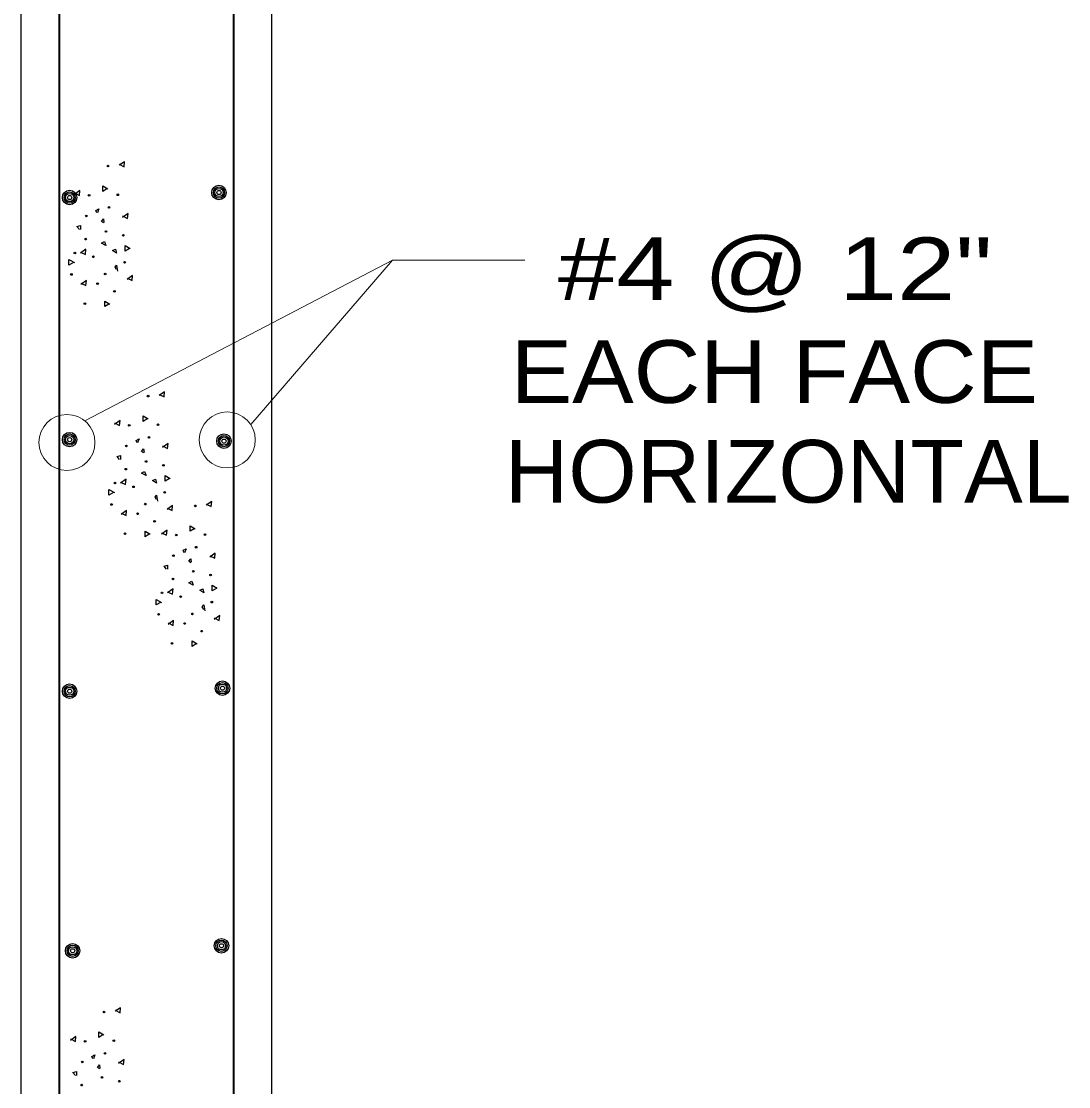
# Model space of a CAD drawing. Extents: x -28.1 to 13.9, y -16.1 to 13.9.
# Drawn here: x -22.697 to -20.607, y 4.395 to 6.521 of the extents above; entities that cross this region are included whole.
import ezdxf
from ezdxf.enums import TextEntityAlignment as Align

# ---------------------------------------------------------------- set-up
doc = ezdxf.new("R2010")
doc.units = 0
doc.header["$LTSCALE"] = 0.05
doc.layers.add('1', color=7, linetype='Continuous', lineweight=13)
doc.layers.add('2', color=7, linetype='Continuous', lineweight=13)

msp = doc.modelspace()

# ---------------------------------------------------------------- linework, layer by layer
at = {"layer": '1', "lineweight": 25}
for p, q in [((-22.19704, 2.64469), (-22.19704, 10.70469)), ((-22.69704, 2.64269), (-22.69704, 10.64469))]:
    msp.add_line(p, q, dxfattribs=at)
at = {"layer": '1', "lineweight": 35}
for p, q in [((-22.62104, 3.38969), (-22.62104, 10.54969)), ((-22.27304, 3.39469), (-22.27304, 10.54969))]:
    msp.add_line(p, q, dxfattribs=at)
at = {"layer": '1'}
for q in [(-22.57004, 5.72369), (-22.23904, 5.71669), (-21.69204, 6.04469)]:
    msp.add_line((-21.95604, 6.04469), q, dxfattribs=at)
at = {"layer": '1', "lineweight": 25}
for centre, radius in [((-22.30257, 6.17941), 0.01445), ((-22.30257, 6.17941), 0.01121), ((-22.30257, 6.17941), 0.00822), ((-22.60057, 6.16941), 0.01445), ((-22.60057, 6.16941), 0.01121), ((-22.60057, 6.16941), 0.00822), ((-22.60057, 6.16941), 0.00415), ((-22.30257, 6.17941), 0.00415), ((-22.60057, 5.68641), 0.01445), ((-22.60057, 5.68641), 0.01121), ((-22.29257, 5.68341), 0.01445), ((-22.60057, 5.68641), 0.00822), ((-22.60057, 5.68641), 0.00415), ((-22.29257, 5.68341), 0.01121), ((-22.29257, 5.68341), 0.00822), ((-22.29257, 5.68341), 0.00415), ((-22.60057, 5.18441), 0.01445), ((-22.60057, 5.18441), 0.01121), ((-22.60057, 5.18441), 0.00822), ((-22.60057, 5.18441), 0.00415), ((-22.29557, 5.19041), 0.01445), ((-22.29557, 5.19041), 0.01121), ((-22.29557, 5.19041), 0.00822), ((-22.29557, 5.19041), 0.00415), ((-22.59457, 4.66641), 0.01445), ((-22.59457, 4.66641), 0.01121), ((-22.29757, 4.67641), 0.01445), ((-22.29757, 4.67641), 0.01121), ((-22.29757, 4.67641), 0.00822), ((-22.29757, 4.67641), 0.00415), ((-22.59457, 4.66641), 0.00822), ((-22.59457, 4.66641), 0.00415)]:
    msp.add_circle(centre, radius, dxfattribs=at)
at = {"layer": '1'}
for centre in [(-22.28604, 5.68569), (-22.60604, 5.68069)]:
    msp.add_circle(centre, 0.0559, dxfattribs=at)
at = {"layer": '2', "lineweight": 25}
for p, q in [((-22.58104, 6.10569), (-22.58604, 6.11169)), ((-22.50104, 5.64669), (-22.50604, 5.65269)), ((-22.40704, 5.42769), (-22.41204, 5.43369)), ((-22.58904, 4.41769), (-22.59404, 4.42369))]:
    msp.add_line(p, q, dxfattribs=at)
for points in [[(-22.50204, 6.23569), (-22.49204, 6.23069), (-22.49104, 6.24069), (-22.50204, 6.23369)], [(-22.52604, 6.18669), (-22.53404, 6.18169), (-22.53404, 6.19269), (-22.52404, 6.18669)], [(-22.59104, 6.17869), (-22.58104, 6.17369), (-22.58004, 6.18369), (-22.59104, 6.17569)], [(-22.54604, 6.13869), (-22.54804, 6.14369), (-22.54204, 6.14669), (-22.54504, 6.13869)], [(-22.53304, 6.11869), (-22.53704, 6.12169), (-22.53304, 6.12669), (-22.53204, 6.11969)], [(-22.49504, 6.13269), (-22.48504, 6.12769), (-22.48404, 6.13769), (-22.49504, 6.12969)], [(-22.58604, 6.11169), (-22.57904, 6.11369), (-22.57904, 6.10569)], [(-22.57904, 6.06069), (-22.56904, 6.05569), (-22.56804, 6.06669), (-22.57904, 6.05869)], [(-22.48104, 6.06769), (-22.49004, 6.06269), (-22.49004, 6.07369), (-22.48004, 6.06769)], [(-22.59304, 6.03969), (-22.60204, 6.03469), (-22.60204, 6.04569), (-22.59104, 6.03969)], [(-22.50704, 6.02569), (-22.51004, 6.03069), (-22.50704, 6.03469), (-22.50504, 6.02269)], [(-22.57804, 5.99869), (-22.56804, 5.99369), (-22.56704, 6.00369), (-22.57804, 5.99569)], [(-22.48604, 6.00869), (-22.47604, 6.00369), (-22.47504, 6.01369), (-22.48604, 6.00569)], [(-22.52204, 5.95669), (-22.53004, 5.95169), (-22.53004, 5.96269), (-22.52004, 5.95669)], [(-22.42204, 5.77669), (-22.41204, 5.77169), (-22.41104, 5.78169), (-22.42204, 5.77469)], [(-22.51104, 5.71969), (-22.50104, 5.71469), (-22.50004, 5.72469), (-22.51104, 5.71669)], [(-22.44604, 5.72769), (-22.45404, 5.72269), (-22.45404, 5.73369), (-22.44404, 5.72769)], [(-22.46604, 5.67969), (-22.46804, 5.68469), (-22.46204, 5.68769), (-22.46504, 5.67969)], [(-22.41504, 5.67369), (-22.40504, 5.66869), (-22.40404, 5.67869), (-22.41504, 5.67069)], [(-22.50604, 5.65269), (-22.49904, 5.65469), (-22.49904, 5.64669)], [(-22.45304, 5.65969), (-22.45704, 5.66269), (-22.45304, 5.66769), (-22.45204, 5.66069)], [(-22.40104, 5.60869), (-22.41004, 5.60369), (-22.41004, 5.61469), (-22.40004, 5.60869)], [(-22.49904, 5.60169), (-22.48904, 5.59669), (-22.48804, 5.60769), (-22.49904, 5.59969)], [(-22.51304, 5.58069), (-22.52204, 5.57569), (-22.52204, 5.58669), (-22.51104, 5.58069)], [(-22.42704, 5.56669), (-22.43004, 5.57169), (-22.42704, 5.57569), (-22.42504, 5.56369)], [(-22.40604, 5.54969), (-22.39604, 5.54469), (-22.39504, 5.55469), (-22.40604, 5.54669)], [(-22.32804, 5.55769), (-22.31804, 5.55269), (-22.31704, 5.56269), (-22.32804, 5.55569)], [(-22.49804, 5.53969), (-22.48804, 5.53469), (-22.48704, 5.54469), (-22.49804, 5.53669)], [(-22.35204, 5.50869), (-22.36004, 5.50369), (-22.36004, 5.51469), (-22.35004, 5.50869)], [(-22.44204, 5.49769), (-22.45004, 5.49269), (-22.45004, 5.50369), (-22.44004, 5.49769)], [(-22.41704, 5.50069), (-22.40704, 5.49569), (-22.40604, 5.50569), (-22.41704, 5.49769)], [(-22.37204, 5.46069), (-22.37404, 5.46569), (-22.36804, 5.46869), (-22.37104, 5.46069)], [(-22.35904, 5.44069), (-22.36304, 5.44369), (-22.35904, 5.44869), (-22.35804, 5.44169)], [(-22.32104, 5.45469), (-22.31104, 5.44969), (-22.31004, 5.45969), (-22.32104, 5.45169)], [(-22.41204, 5.43369), (-22.40504, 5.43569), (-22.40504, 5.42769)], [(-22.40504, 5.38269), (-22.39504, 5.37769), (-22.39404, 5.38869), (-22.40504, 5.38069)], [(-22.30704, 5.38969), (-22.31604, 5.38469), (-22.31604, 5.39569), (-22.30604, 5.38969)], [(-22.41904, 5.36169), (-22.42804, 5.35669), (-22.42804, 5.36769), (-22.41704, 5.36169)], [(-22.33304, 5.34769), (-22.33604, 5.35269), (-22.33304, 5.35669), (-22.33104, 5.34469)], [(-22.40404, 5.32069), (-22.39404, 5.31569), (-22.39304, 5.32569), (-22.40404, 5.31769)], [(-22.31204, 5.33069), (-22.30204, 5.32569), (-22.30104, 5.33569), (-22.31204, 5.32769)], [(-22.34804, 5.27869), (-22.35604, 5.27369), (-22.35604, 5.28469), (-22.34604, 5.27869)], [(-22.51004, 4.54769), (-22.50004, 4.54269), (-22.49904, 4.55269), (-22.51004, 4.54569)], [(-22.59904, 4.49069), (-22.58904, 4.48569), (-22.58804, 4.49569), (-22.59904, 4.48769)], [(-22.53404, 4.49869), (-22.54204, 4.49369), (-22.54204, 4.50469), (-22.53204, 4.49869)], [(-22.55404, 4.45069), (-22.55604, 4.45569), (-22.55004, 4.45869), (-22.55304, 4.45069)], [(-22.50304, 4.44469), (-22.49304, 4.43969), (-22.49204, 4.44969), (-22.50304, 4.44169)], [(-22.59404, 4.42369), (-22.58704, 4.42569), (-22.58704, 4.41769)], [(-22.54104, 4.43069), (-22.54504, 4.43369), (-22.54104, 4.43869), (-22.54004, 4.43169)]]:
    msp.add_lwpolyline(points, dxfattribs=at)
for points in [[(-22.52804, 6.07369), (-22.53704, 6.07869), (-22.53104, 6.08169)], [(-22.50704, 6.05869), (-22.51504, 6.06369), (-22.50904, 6.06669)], [(-22.44804, 5.61469), (-22.45704, 5.61969), (-22.45104, 5.62269)], [(-22.42704, 5.59969), (-22.43504, 5.60469), (-22.42904, 5.60769)], [(-22.35404, 5.39569), (-22.36304, 5.40069), (-22.35704, 5.40369)], [(-22.33304, 5.38069), (-22.34104, 5.38569), (-22.33504, 5.38869)]]:
    msp.add_lwpolyline(points, close=True, dxfattribs=at)
for centre in [(-22.52392, 6.23219), (-22.56167, 6.17394), (-22.50442, 6.17494), (-22.52217, 6.14969), (-22.56742, 6.13269), (-22.52792, 6.10169), (-22.56842, 6.08644), (-22.49342, 6.09419), (-22.59017, 6.05869), (-22.55317, 6.05119), (-22.49092, 6.04019), (-22.59692, 6.01594), (-22.52967, 6.01669), (-22.54492, 5.99744), (-22.51117, 5.98219), (-22.57017, 5.95769), (-22.44392, 5.77319), (-22.48167, 5.71494), (-22.42442, 5.71594), (-22.44217, 5.69069), (-22.48742, 5.67369), (-22.44792, 5.64269), (-22.41342, 5.63519), (-22.48842, 5.62744), (-22.51017, 5.59969), (-22.47317, 5.59219), (-22.41092, 5.58119), (-22.51692, 5.55694), (-22.44967, 5.55769), (-22.34992, 5.55419), (-22.46492, 5.53844), (-22.43117, 5.52319), (-22.49017, 5.49869), (-22.38767, 5.49594), (-22.33042, 5.49694), (-22.34817, 5.47169), (-22.39342, 5.45469), (-22.35392, 5.42369), (-22.39442, 5.40844), (-22.31942, 5.41619), (-22.41617, 5.38069), (-22.37917, 5.37319), (-22.31692, 5.36219), (-22.42292, 5.33794), (-22.35567, 5.33869), (-22.37092, 5.31944), (-22.33717, 5.30419), (-22.39617, 5.27969), (-22.53192, 4.54419), (-22.56967, 4.48594), (-22.51242, 4.48694), (-22.57542, 4.44469), (-22.53017, 4.46169), (-22.53592, 4.41369), (-22.50142, 4.40619), (-22.57642, 4.39844)]:
    msp.add_circle(centre, 0.00162, dxfattribs=at)

# ---------------------------------------------------------------- texts
at = {"layer": '1', "width": 1.25}
msp.add_text('#4 @ 12"', height=0.125, dxfattribs=at).set_placement((-21.62604, 5.96469))
at = {"layer": '1'}
for s, width, p in [('EACH FACE', 1.1, (-21.1941, 5.75969)), ('HORIZONTAL', 1.05, (-21.1666, 5.56069))]:
    msp.add_text(s, height=0.125, dxfattribs=dict(at, width=width)).set_placement(p, align=Align.CENTER)

doc.saveas('drawing.dxf')
